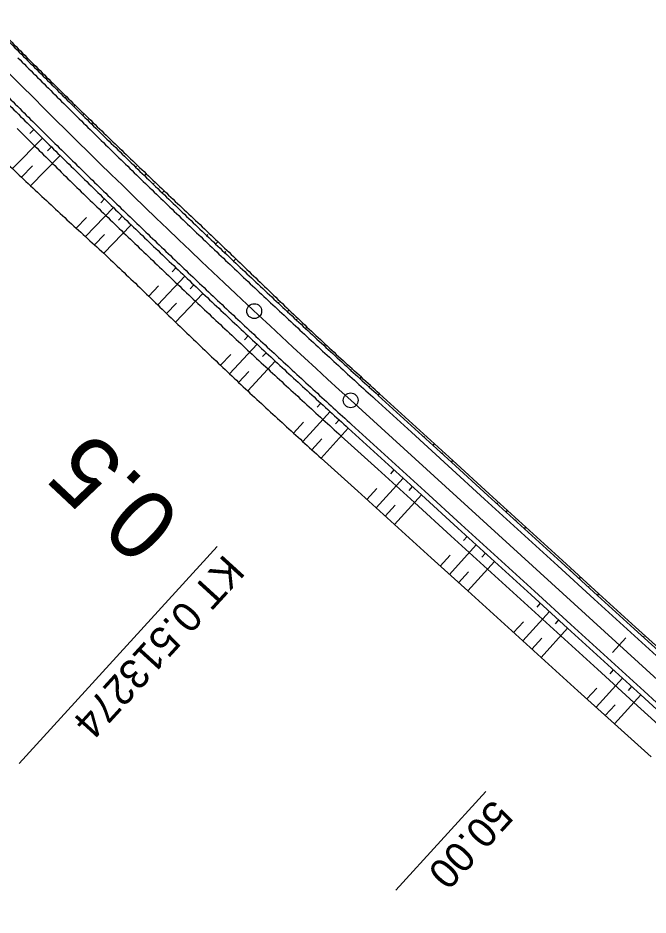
# Model space of a CAD drawing. Extents: x -481645 to -478728, y -1113199 to -1110710.
# Drawn here: x -481388.3 to -481324.6, y -1112998.4 to -1112907.7 of the extents above; entities that cross this region are included whole.
import ezdxf

# ---------------------------------------------------------------- set-up
doc = ezdxf.new("R2010")
doc.units = 0
for name, color, linetype in [('Vrstva 41', 7, 'Continuous'), ('Vrstva 42', 7, 'Continuous'), ('Vrstva 43', 7, 'Continuous'), ('Vrstva 44', 7, 'Continuous'), ('Vrstva 45', 7, 'Continuous'), ('Vrstva 46', 7, 'Continuous'), ('Vrstva 47', 7, 'Continuous'), ('Vrstva 48', 7, 'Continuous'), ('Vrstva 49', 7, 'Continuous'), ('Vrstva 50', 7, 'Continuous'), ('Vrstva 51', 7, 'Continuous')]:
    doc.layers.add(name, color=color, linetype=linetype)

msp = doc.modelspace()

# ---------------------------------------------------------------- linework, layer by layer
at = {"layer": 'Vrstva 41'}
msp.add_line((-481354.685, -1112946.378), (-481297.645, -1112998.401), dxfattribs=at)
msp.add_arc((-480680.814, -1112207.528), 1000, 224.728347, 227.633472, dxfattribs=at)
at = {"layer": 'Vrstva 42'}
for p, q in [((-481351.767, -1112945.741), (-481348.073, -1112949.11)), ((-481348.073, -1112949.11), (-481344.378, -1112952.478)), ((-481357.676, -1112952.219), (-481353.971, -1112955.577)), ((-481344.378, -1112952.478), (-481340.683, -1112955.847)), ((-481353.971, -1112955.577), (-481350.266, -1112958.935)), ((-481340.683, -1112955.847), (-481336.988, -1112959.215)), ((-481350.266, -1112958.935), (-481346.563, -1112962.294)), ((-481336.988, -1112959.215), (-481333.292, -1112962.584)), ((-481346.563, -1112962.294), (-481342.858, -1112965.651)), ((-481333.292, -1112962.584), (-481329.598, -1112965.952)), ((-481342.858, -1112965.651), (-481339.154, -1112969.01)), ((-481329.598, -1112965.952), (-481325.886, -1112969.303)), ((-481339.154, -1112969.01), (-481335.449, -1112972.368)), ((-481325.886, -1112969.303), (-481322.188, -1112972.668)), ((-481335.449, -1112972.368), (-481331.745, -1112975.727)), ((-481331.745, -1112975.727), (-481328.022, -1112979.065)), ((-481328.022, -1112979.065), (-481324.301, -1112982.404))]:
    msp.add_line(p, q, dxfattribs=at)
for centre, radius, start, end in [((-479258.593, -1110808.225), 2992.76, 224.550017, 224.645628), ((-480681.84, -1112206.504), 997.583, 224.950853, 225.237333), ((-480686.361, -1112202.081), 997.56, 225.600597, 225.887086), ((-480686.387, -1112202.11), 997.521, 225.886986, 226.173475), ((-480697.007, -1112191.858), 1006.58, 226.436722, 226.723272), ((-480686.557, -1112202.001), 997.482, 226.184886, 226.471375), ((-480699.383, -1112189.792), 1006.459, 226.902394, 227.188967), ((-480687.664, -1112201.012), 997.438, 226.556611, 226.843103), ((-480703.004, -1112186.645), 1006.319, 227.461944, 227.748556), ((-480679.681, -1112208.608), 997.418, 226.210094, 226.496575), ((-480684.812, -1112203.71), 1006.229, 226.328314, 226.614797), ((-480672.042, -1112215.887), 997.453, 225.890458, 226.176958), ((-480673.733, -1112214.328), 1006.239, 225.741017, 226.027511), ((-480672.182, -1112215.67), 997.513, 226.191403, 226.477903), ((-480674.239, -1112213.774), 1006.287, 226.070111, 226.356603), ((-480677.508, -1112210.593), 997.554, 226.9005, 227.186983), ((-480674.506, -1112213.458), 1006.331, 226.380047, 226.666536), ((-481690.021, -1113312.304), 498.782, 47.30015, 47.87359), ((-480681.85, -1112206.573), 1006.349, 227.239672, 227.526153), ((-481021.065, -1112578.22), 503.173, 227.44009, 228.0118)]:
    msp.add_arc(centre, radius, start, end, dxfattribs=at)
at = {"layer": 'Vrstva 43'}
for p, q in [((-481355.644, -1112949.992), (-481351.946, -1112953.357)), ((-481351.946, -1112953.357), (-481348.248, -1112956.722)), ((-481348.248, -1112956.722), (-481344.55, -1112960.087)), ((-481344.55, -1112960.087), (-481340.852, -1112963.452)), ((-481340.852, -1112963.452), (-481337.154, -1112966.817)), ((-481337.154, -1112966.817), (-481333.455, -1112970.182)), ((-481333.455, -1112970.182), (-481329.757, -1112973.547)), ((-481329.757, -1112973.547), (-481326.059, -1112976.912)), ((-481326.059, -1112976.912), (-481322.361, -1112980.277))]:
    msp.add_line(p, q, dxfattribs=at)
for centre, radius, start, end in [((-480681.643, -1112206.709), 1003.366, 225.22065, 225.507131), ((-480681.645, -1112206.715), 1003.361, 225.506956, 225.793436), ((-480681.651, -1112206.717), 1003.355, 225.793611, 226.080092), ((-480681.655, -1112206.721), 1003.349, 226.080092, 226.366572), ((-480681.657, -1112206.728), 1003.343, 226.366397, 226.652878), ((-480681.659, -1112206.734), 1003.337, 226.652703, 226.939183), ((-480681.669, -1112206.732), 1003.331, 226.939706, 227.226186), ((-480681.669, -1112206.74), 1003.326, 227.225836, 227.512317), ((-481019.477, -1112577.627), 501.661, 227.35226, 227.92457)]:
    msp.add_arc(centre, radius, start, end, dxfattribs=at)
at = {"layer": 'Vrstva 44'}
for p, q in [((-481351.893, -1112945.879), (-481348.199, -1112949.248)), ((-481354.925, -1112949.203), (-481351.231, -1112952.573)), ((-481348.199, -1112949.248), (-481344.504, -1112952.617)), ((-481351.231, -1112952.573), (-481347.537, -1112955.942)), ((-481344.504, -1112952.617), (-481340.81, -1112955.987)), ((-481347.537, -1112955.942), (-481343.843, -1112959.311)), ((-481340.81, -1112955.987), (-481337.116, -1112959.356)), ((-481343.843, -1112959.311), (-481340.148, -1112962.681)), ((-481337.116, -1112959.356), (-481333.422, -1112962.725)), ((-481340.148, -1112962.681), (-481336.454, -1112966.05)), ((-481333.422, -1112962.725), (-481329.727, -1112966.095)), ((-481336.454, -1112966.05), (-481332.76, -1112969.42)), ((-481329.727, -1112966.095), (-481326.033, -1112969.464)), ((-481332.76, -1112969.42), (-481329.066, -1112972.789)), ((-481326.033, -1112969.464), (-481322.339, -1112972.833)), ((-481329.066, -1112972.789), (-481325.371, -1112976.158)), ((-481325.371, -1112976.158), (-481321.677, -1112979.528))]:
    msp.add_line(p, q, dxfattribs=at)
for centre, radius, start, end in [((-479264.402, -1110801.897), 2993.25, 224.714353, 224.809956), ((-480680.814, -1112207.528), 997.75, 224.8676, 225.154081), ((-480680.814, -1112207.528), 1002.25, 224.867603, 225.154083), ((-480680.814, -1112207.528), 997.75, 225.154081, 225.440561), ((-480680.814, -1112207.528), 1002.25, 225.154081, 225.440561), ((-480680.814, -1112207.528), 997.75, 225.440561, 225.727042), ((-480680.814, -1112207.528), 1002.25, 225.440561, 225.727042), ((-480680.814, -1112207.528), 997.75, 225.727039, 226.013519), ((-480680.814, -1112207.528), 1002.25, 225.727042, 226.013522), ((-480680.814, -1112207.528), 997.75, 226.013519, 226.3), ((-480680.814, -1112207.528), 1002.25, 226.013519, 226.3), ((-480680.814, -1112207.528), 997.75, 226.3, 226.586481), ((-480680.814, -1112207.528), 1002.25, 226.3, 226.586481), ((-480680.814, -1112207.528), 997.75, 226.586478, 226.872958), ((-480680.814, -1112207.528), 1002.25, 226.586478, 226.872958), ((-480680.814, -1112207.528), 997.75, 226.872958, 227.159439), ((-480680.814, -1112207.528), 1002.25, 226.872958, 227.159439), ((-480680.814, -1112207.528), 997.75, 227.159439, 227.445919), ((-480680.814, -1112207.528), 1002.25, 227.159439, 227.445919), ((-481017.168, -1112575.966), 498.875, 227.28536, 227.85876), ((-481018.687, -1112577.626), 501.125, 227.28571, 227.85822)]:
    msp.add_arc(centre, radius, start, end, dxfattribs=at)
at = {"layer": 'Vrstva 45'}
for p, q in [((-481352.23, -1112946.248), (-481348.536, -1112949.617)), ((-481354.588, -1112948.834), (-481350.894, -1112952.203)), ((-481348.536, -1112949.617), (-481344.841, -1112952.987)), ((-481350.894, -1112952.203), (-481347.2, -1112955.573)), ((-481344.841, -1112952.987), (-481341.147, -1112956.356)), ((-481347.2, -1112955.573), (-481343.506, -1112958.942)), ((-481341.147, -1112956.356), (-481337.453, -1112959.725)), ((-481343.506, -1112958.942), (-481339.811, -1112962.311)), ((-481337.453, -1112959.725), (-481333.759, -1112963.095)), ((-481339.811, -1112962.311), (-481336.117, -1112965.681)), ((-481333.759, -1112963.095), (-481330.064, -1112966.464)), ((-481336.117, -1112965.681), (-481332.423, -1112969.05)), ((-481330.064, -1112966.464), (-481326.37, -1112969.833)), ((-481332.423, -1112969.05), (-481328.729, -1112972.419)), ((-481326.37, -1112969.833), (-481322.676, -1112973.203)), ((-481328.729, -1112972.419), (-481325.034, -1112975.789)), ((-481325.034, -1112975.789), (-481321.34, -1112979.158))]:
    msp.add_line(p, q, dxfattribs=at)
for centre, radius, start, end in [((-480680.814, -1112207.528), 998.25, 224.8676, 225.154081), ((-480680.814, -1112207.528), 1001.75, 224.867603, 225.154083), ((-480680.814, -1112207.528), 998.25, 225.154081, 225.440561), ((-480680.814, -1112207.528), 1001.75, 225.154081, 225.440561), ((-480680.814, -1112207.528), 998.25, 225.440561, 225.727042), ((-480680.814, -1112207.528), 1001.75, 225.440561, 225.727042), ((-480680.814, -1112207.528), 998.25, 225.727039, 226.013519), ((-480680.814, -1112207.528), 1001.75, 225.727039, 226.013519), ((-480680.814, -1112207.528), 998.25, 226.013519, 226.3), ((-480680.814, -1112207.528), 1001.75, 226.013519, 226.3), ((-480680.814, -1112207.528), 998.25, 226.3, 226.586481), ((-480680.814, -1112207.528), 1001.75, 226.3, 226.586481), ((-480680.814, -1112207.528), 998.25, 226.586478, 226.872958), ((-480680.814, -1112207.528), 1001.75, 226.586478, 226.872958), ((-480680.814, -1112207.528), 998.25, 226.872958, 227.159439), ((-480680.814, -1112207.528), 1001.75, 226.872958, 227.159439), ((-480680.814, -1112207.528), 998.25, 227.159439, 227.445919), ((-480680.814, -1112207.528), 1001.75, 227.159439, 227.445919), ((-481017.336, -1112576.151), 499.125, 227.28539, 227.8587), ((-481018.518, -1112577.441), 500.875, 227.28567, 227.85828)]:
    msp.add_arc(centre, radius, start, end, dxfattribs=at)
at = {"layer": 'Vrstva 46'}
for p, q in [((-481352.23, -1112946.248), (-481348.536, -1112949.617)), ((-481354.588, -1112948.834), (-481350.894, -1112952.203)), ((-481348.536, -1112949.617), (-481344.841, -1112952.987)), ((-481350.894, -1112952.203), (-481347.2, -1112955.573)), ((-481344.841, -1112952.987), (-481341.147, -1112956.356)), ((-481347.2, -1112955.573), (-481343.506, -1112958.942)), ((-481341.147, -1112956.356), (-481337.453, -1112959.725)), ((-481343.506, -1112958.942), (-481339.811, -1112962.311)), ((-481337.453, -1112959.725), (-481333.759, -1112963.095)), ((-481339.811, -1112962.311), (-481336.117, -1112965.681)), ((-481333.759, -1112963.095), (-481330.064, -1112966.464)), ((-481336.117, -1112965.681), (-481332.423, -1112969.05)), ((-481330.064, -1112966.464), (-481326.37, -1112969.833)), ((-481332.423, -1112969.05), (-481328.729, -1112972.419)), ((-481326.37, -1112969.833), (-481322.676, -1112973.203)), ((-481328.729, -1112972.419), (-481325.034, -1112975.789)), ((-481325.034, -1112975.789), (-481321.34, -1112979.158))]:
    msp.add_line(p, q, dxfattribs=at)
for centre, radius, start, end in [((-480680.814, -1112207.528), 998.25, 224.8676, 225.154081), ((-480680.814, -1112207.528), 1001.75, 224.867603, 225.154083), ((-480680.814, -1112207.528), 998.25, 225.154081, 225.440561), ((-480680.814, -1112207.528), 1001.75, 225.154081, 225.440561), ((-480680.814, -1112207.528), 998.25, 225.440561, 225.727042), ((-480680.814, -1112207.528), 1001.75, 225.440561, 225.727042), ((-480680.814, -1112207.528), 998.25, 225.727039, 226.013519), ((-480680.814, -1112207.528), 1001.75, 225.727039, 226.013519), ((-480680.814, -1112207.528), 998.25, 226.013519, 226.3), ((-480680.814, -1112207.528), 1001.75, 226.013519, 226.3), ((-480680.814, -1112207.528), 998.25, 226.3, 226.586481), ((-480680.814, -1112207.528), 1001.75, 226.3, 226.586481), ((-480680.814, -1112207.528), 998.25, 226.586478, 226.872958), ((-480680.814, -1112207.528), 1001.75, 226.586478, 226.872958), ((-480680.814, -1112207.528), 998.25, 226.872958, 227.159439), ((-480680.814, -1112207.528), 1001.75, 226.872958, 227.159439), ((-480680.814, -1112207.528), 998.25, 227.159439, 227.445919), ((-480680.814, -1112207.528), 1001.75, 227.159439, 227.445919), ((-481017.336, -1112576.151), 499.125, 227.28539, 227.8587), ((-481018.518, -1112577.441), 500.875, 227.28567, 227.85828)]:
    msp.add_arc(centre, radius, start, end, dxfattribs=at)
at = {"layer": 'Vrstva 47'}
for p, q in [((-481328.223, -1112971.865), (-481326.876, -1112970.388)), ((-481341.027, -1112985.903), (-481350.124, -1112995.878))]:
    msp.add_line(p, q, dxfattribs=at)
at = {"layer": 'Vrstva 48'}
msp.add_line((-481368.162, -1112961.155), (-481388.176, -1112983.098), dxfattribs=at)
msp.add_circle((-481354.685, -1112946.378), 0.75, dxfattribs=at)
at = {"layer": 'Vrstva 49'}
msp.add_circle((-481364.432, -1112937.368), 0.75, dxfattribs=at)
at = {"layer": 'Vrstva 50'}
for p, q in [((-481387.958, -1112911.412), (-481387.842, -1112911.297)), ((-481383.545, -1112915.818), (-481383.481, -1112915.754)), ((-481383.418, -1112915.69), (-481383.418, -1112915.69)), ((-481382.659, -1112916.696), (-481382.526, -1112916.561)), ((-481381.772, -1112917.572), (-481381.702, -1112917.501)), ((-481381.632, -1112917.43), (-481381.632, -1112917.43)), ((-481380.884, -1112918.448), (-481380.737, -1112918.299)), ((-481376.427, -1112922.81), (-481376.337, -1112922.717)), ((-481376.247, -1112922.624), (-481376.247, -1112922.624)), ((-481375.533, -1112923.679), (-481375.346, -1112923.486)), ((-481374.637, -1112924.546), (-481374.54, -1112924.446)), ((-481374.443, -1112924.346), (-481374.443, -1112924.346)), ((-481373.74, -1112925.413), (-481373.54, -1112925.206)), ((-481369.24, -1112929.73), (-481369.125, -1112929.609)), ((-481369.01, -1112929.488), (-481369.01, -1112929.488)), ((-481368.336, -1112930.59), (-481368.108, -1112930.35)), ((-481367.432, -1112931.449), (-481367.318, -1112931.33)), ((-481367.205, -1112931.21), (-481367.205, -1112931.21)), ((-481366.527, -1112932.306), (-481366.301, -1112932.068)), ((-481361.811, -1112936.394), (-481361.811, -1112936.394)), ((-481361.983, -1112936.578), (-481361.897, -1112936.486)), ((-481361.072, -1112937.429), (-481360.91, -1112937.255)), ((-481360.159, -1112938.279), (-481360.083, -1112938.198)), ((-481360.007, -1112938.116), (-481360.007, -1112938.116)), ((-481359.245, -1112939.127), (-481359.103, -1112938.975)), ((-481354.659, -1112943.353), (-481354.596, -1112943.284)), ((-481354.534, -1112943.216), (-481354.534, -1112943.216)), ((-481353.739, -1112944.195), (-481353.613, -1112944.058)), ((-481352.817, -1112945.036), (-481352.754, -1112944.968)), ((-481352.691, -1112944.899), (-481352.691, -1112944.899)), ((-481351.893, -1112945.879), (-481351.767, -1112945.741)), ((-481347.149, -1112949.952), (-481347.149, -1112949.952)), ((-481347.275, -1112950.09), (-481347.212, -1112950.021)), ((-481346.352, -1112950.933), (-481346.225, -1112950.794)), ((-481345.428, -1112951.775), (-481345.365, -1112951.706)), ((-481345.302, -1112951.636), (-481345.302, -1112951.636)), ((-481344.504, -1112952.617), (-481344.378, -1112952.478)), ((-481339.887, -1112956.829), (-481339.823, -1112956.759)), ((-481339.759, -1112956.689), (-481339.759, -1112956.689)), ((-481338.963, -1112957.671), (-481338.835, -1112957.531)), ((-481338.04, -1112958.514), (-481337.976, -1112958.444)), ((-481337.911, -1112958.373), (-481337.911, -1112958.373)), ((-481337.116, -1112959.356), (-481336.988, -1112959.215)), ((-481332.498, -1112963.568), (-481332.434, -1112963.497)), ((-481332.369, -1112963.426), (-481332.369, -1112963.426)), ((-481331.575, -1112964.41), (-481331.445, -1112964.268)), ((-481330.651, -1112965.252), (-481330.586, -1112965.181)), ((-481330.521, -1112965.11), (-481330.521, -1112965.11)), ((-481329.727, -1112966.095), (-481329.598, -1112965.952)), ((-481325.11, -1112970.306), (-481325.036, -1112970.225)), ((-481324.962, -1112970.144), (-481324.962, -1112970.144))]:
    msp.add_line(p, q, dxfattribs=at)
at = {"layer": 'Vrstva 51'}
for p, q in [((-481386.715, -1112919.012), (-481387.108, -1112919.409)), ((-481385.825, -1112919.894), (-481388.87, -1112922.972)), ((-481384.934, -1112920.775), (-481385.326, -1112921.172)), ((-481384.042, -1112921.654), (-481387.04, -1112924.699)), ((-481386.836, -1112922.702), (-481387.956, -1112923.836)), ((-481379.565, -1112926.036), (-481379.951, -1112926.432)), ((-481378.666, -1112926.909), (-481381.499, -1112929.829)), ((-481381.382, -1112927.904), (-481382.428, -1112928.98)), ((-481377.766, -1112927.78), (-481378.15, -1112928.176)), ((-481376.865, -1112928.651), (-481379.638, -1112931.524)), ((-481379.551, -1112929.625), (-481380.569, -1112930.677)), ((-481372.345, -1112932.987), (-481372.722, -1112933.383)), ((-481371.437, -1112933.851), (-481374.186, -1112936.742)), ((-481374.094, -1112934.822), (-481375.089, -1112935.866)), ((-481370.529, -1112934.714), (-481370.904, -1112935.11)), ((-481369.619, -1112935.575), (-481372.378, -1112938.491)), ((-481372.282, -1112936.562), (-481373.283, -1112937.617)), ((-481365.056, -1112939.866), (-481365.426, -1112940.262)), ((-481364.14, -1112940.721), (-481366.922, -1112943.706)), ((-481366.814, -1112941.748), (-481367.834, -1112942.84)), ((-481363.223, -1112941.574), (-481363.59, -1112941.97)), ((-481362.305, -1112942.427), (-481365.094, -1112945.435)), ((-481364.983, -1112943.468), (-481366.009, -1112944.571)), ((-481357.698, -1112946.672), (-481358.06, -1112947.067)), ((-481356.774, -1112947.517), (-481359.531, -1112950.536)), ((-481359.442, -1112948.576), (-481360.462, -1112949.69)), ((-481355.849, -1112948.361), (-481356.209, -1112948.756)), ((-481354.925, -1112949.203), (-481357.676, -1112952.219)), ((-481357.586, -1112950.265), (-481358.602, -1112951.38)), ((-481350.308, -1112953.415), (-481350.665, -1112953.806)), ((-481349.384, -1112954.257), (-481352.119, -1112957.256)), ((-481352.034, -1112955.307), (-481353.045, -1112956.416)), ((-481348.46, -1112955.1), (-481348.816, -1112955.49)), ((-481347.537, -1112955.942), (-481350.266, -1112958.935)), ((-481350.182, -1112956.988), (-481351.192, -1112958.095)), ((-481342.919, -1112960.154), (-481343.272, -1112960.541)), ((-481341.996, -1112960.996), (-481344.71, -1112963.973)), ((-481344.63, -1112962.03), (-481345.636, -1112963.133)), ((-481340.148, -1112962.681), (-481342.858, -1112965.651)), ((-481341.072, -1112961.838), (-481341.424, -1112962.224)), ((-481342.78, -1112963.712), (-481343.784, -1112964.812)), ((-481335.531, -1112966.892), (-481335.88, -1112967.275)), ((-481334.607, -1112967.735), (-481337.301, -1112970.689)), ((-481337.228, -1112968.754), (-481338.228, -1112969.85)), ((-481333.683, -1112968.577), (-481334.032, -1112968.959)), ((-481332.76, -1112969.42), (-481335.449, -1112972.368)), ((-481335.378, -1112970.434), (-481336.375, -1112971.528)), ((-481327.219, -1112974.474), (-481329.884, -1112977.396)), ((-481328.142, -1112973.631), (-481328.488, -1112974.01)), ((-481326.295, -1112975.316), (-481326.64, -1112975.694)), ((-481329.824, -1112975.474), (-481330.814, -1112976.561)), ((-481325.371, -1112976.158), (-481328.022, -1112979.065)), ((-481327.968, -1112977.15), (-481328.953, -1112978.23))]:
    msp.add_line(p, q, dxfattribs=at)

# ---------------------------------------------------------------- texts
at = {"layer": 'Vrstva 47'}
msp.add_text('50.00', height=3, rotation=227.63348, dxfattribs=at).set_placement((-481340.287, -1112986.577))
at = {"layer": 'Vrstva 48'}
msp.add_text('KT 0.513274', height=2.999, rotation=227.63348, dxfattribs=at).set_placement((-481367.423, -1112961.828))
at = {"layer": 'Vrstva 49'}
msp.add_text('0.5', height=7, rotation=136.82733, dxfattribs=at).set_placement((-481371.505, -1112958.157))

doc.saveas('drawing.dxf')
